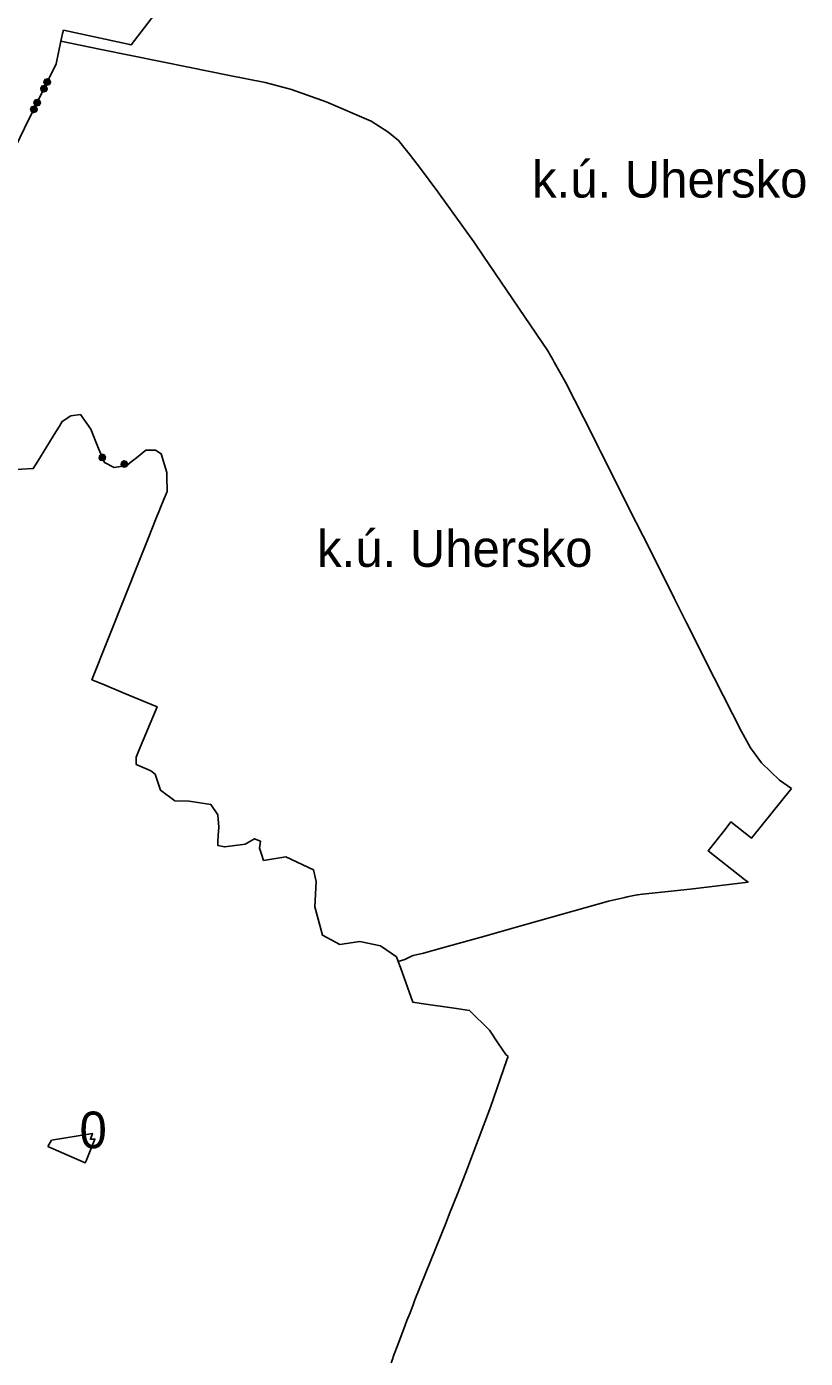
# Model space of a CAD drawing. Extents: x -633893 to -630895, y -1069360 to -1065553.
# Drawn here: x -631779 to -630930, y -1068278 to -1066826 of the extents above; entities that cross this region are included whole.
import ezdxf

# ---------------------------------------------------------------- set-up
doc = ezdxf.new("R2010")
doc.units = 0
for name, color, linetype in [('HRA_KU', 7, 'Continuous'), ('Level 255', 7, 'Continuous'), ('OVNE_PRE', 7, 'Continuous'), ('OVNI_POP', 7, 'Continuous'), ('OVNI_SET', 7, 'Continuous')]:
    doc.layers.add(name, color=color, linetype=linetype)

msp = doc.modelspace()

# ---------------------------------------------------------------- linework, layer by layer
at = {"layer": 'HRA_KU'}
for points in [[(-631889.4, -1067314.4), (-631867.8, -1067252.2), (-631854.9, -1067204.9), (-631851.7, -1067193.5), (-631846.1, -1067157.2), (-631844.8, -1067152), (-631838.9, -1067129.9), (-631829.2, -1067093), (-631816.3, -1067044.3), (-631810.3, -1067021.7), (-631800.1, -1066987.2), (-631791.3, -1066957.2), (-631781.2, -1066936.4), (-631746.9, -1066866.1), (-631741.5, -1066841.4)], [(-631762.5, -1066890.6), (-631759.9, -1066889.8), (-631757.5, -1066890.9), (-631756.6, -1066893.5), (-631757.8, -1066895.9), (-631760.3, -1066896.8), (-631762.8, -1066895.6), (-631763.6, -1066893.1), (-631762.5, -1066890.6), (-631762.2, -1066891.1), (-631763.3, -1066893.2), (-631762.9, -1066894.3), (-631761.2, -1066890.7), (-631760.1, -1066890.3), (-631762.5, -1066895.4), (-631761.8, -1066895.7), (-631759.4, -1066890.7), (-631758.7, -1066891), (-631761.1, -1066896.1), (-631760.4, -1066896.4), (-631757.9, -1066891.4), (-631757.6, -1066892.5), (-631759.3, -1066896.1), (-631758.3, -1066895.7), (-631757.2, -1066893.5)], [(-631758.9, -1066883.3), (-631756.3, -1066882.4), (-631753.9, -1066883.6), (-631753, -1066886.1), (-631754.2, -1066888.5), (-631756.8, -1066889.4), (-631759.2, -1066888.2), (-631760.1, -1066885.7), (-631758.9, -1066883.3), (-631758.6, -1066883.7), (-631759.7, -1066885.9), (-631759.3, -1066886.9), (-631757.6, -1066883.3), (-631756.5, -1066883), (-631759, -1066888), (-631758.2, -1066888.4), (-631755.8, -1066883.3), (-631755.1, -1066883.7), (-631757.5, -1066888.7), (-631756.8, -1066889.1), (-631754.4, -1066884), (-631754, -1066885.1), (-631755.7, -1066888.7), (-631754.7, -1066888.3), (-631753.6, -1066886.2)], [(-631769.8, -1066905.8), (-631767.3, -1066904.9), (-631764.8, -1066906.1), (-631764, -1066908.6), (-631765.2, -1066911), (-631767.7, -1066911.9), (-631770.1, -1066910.7), (-631771, -1066908.2), (-631769.8, -1066905.8), (-631769.5, -1066906), (-631770.5, -1066908.2), (-631770.2, -1066909.2), (-631768.4, -1066905.6), (-631767.4, -1066905.3), (-631769.8, -1066910.3), (-631769.1, -1066910.7), (-631766.6, -1066905.6), (-631765.9, -1066906), (-631768.4, -1066911), (-631767.7, -1066911.4), (-631765.2, -1066906.3), (-631764.8, -1066907.4), (-631766.6, -1066911), (-631765.5, -1066910.6), (-631764.5, -1066908.5)], [(-631773.4, -1066913.1), (-631770.9, -1066912.2), (-631768.4, -1066913.4), (-631767.6, -1066916), (-631768.7, -1066918.4), (-631771.3, -1066919.3), (-631773.7, -1066918.1), (-631774.6, -1066915.5), (-631773.4, -1066913.1), (-631773.1, -1066913.4), (-631774.1, -1066915.5), (-631773.8, -1066916.6), (-631772, -1066913), (-631770.9, -1066912.6), (-631773.4, -1066917.7), (-631772.7, -1066918), (-631770.2, -1066913), (-631769.5, -1066913.3), (-631772, -1066918.4), (-631771.2, -1066918.7), (-631768.8, -1066913.7), (-631768.4, -1066914.8), (-631770.2, -1066918.4), (-631769.1, -1066918), (-631768.1, -1066915.8)], [(-631797.1, -1067308.9), (-631771.7, -1067307.4), (-631766.7, -1067299.3), (-631747, -1067267.3), (-631743.3, -1067261.3), (-631740.1, -1067256), (-631730.9, -1067250.1), (-631720.4, -1067248.6), (-631709.1, -1067264.5), (-631700.5, -1067285.5), (-631694.2, -1067300.8), (-631683.7, -1067306.3), (-631669.6, -1067304.1), (-631664.9, -1067300.2), (-631659.1, -1067295.6), (-631649, -1067287.4), (-631638.6, -1067287.2), (-631632.4, -1067291.2), (-631626.2, -1067311.8), (-631626.1, -1067316.1), (-631625.9, -1067332.3), (-631629.7, -1067341.8), (-631632.9, -1067349.8), (-631634.8, -1067354.6), (-631636.2, -1067358), (-631638.3, -1067363.5), (-631645.7, -1067382), (-631658, -1067412.7), (-631670.1, -1067443.1), (-631690.7, -1067494.9), (-631707.8, -1067537.7), (-631695.9, -1067542.7), (-631673.6, -1067551.9), (-631636.7, -1067567.1), (-631656.6, -1067614.8), (-631659.7, -1067622.2), (-631659.4, -1067630), (-631646.8, -1067635.5), (-631643.7, -1067636.9), (-631638.8, -1067640.7), (-631635, -1067652.6), (-631633.2, -1067658.2), (-631617.5, -1067669.8), (-631601.6, -1067670.1), (-631578, -1067673.9), (-631570.5, -1067684.9), (-631569.5, -1067698.5), (-631570, -1067707.6), (-631570.4, -1067714.4), (-631570.6, -1067718.3), (-631563.4, -1067720), (-631543.1, -1067717.4), (-631540.7, -1067717.1), (-631530.4, -1067711.1), (-631524, -1067713.9), (-631525.2, -1067721.4), (-631522.9, -1067728), (-631520.6, -1067734.8), (-631496.5, -1067730.8), (-631466.1, -1067745.1), (-631463.2, -1067757.7), (-631464.9, -1067785.2), (-631456.5, -1067816.4), (-631437.6, -1067826.3), (-631415.7, -1067823.2), (-631393.3, -1067828), (-631375.6, -1067839.9), (-631373.8, -1067845.1)], [(-631694.3, -1067292.6), (-631693, -1067295), (-631693.8, -1067297.6), (-631696.1, -1067298.8), (-631698.7, -1067298.1), (-631700, -1067295.7), (-631699.2, -1067293.1), (-631696.9, -1067291.8), (-631694.3, -1067292.6), (-631694.5, -1067293), (-631696.8, -1067292.3), (-631697.8, -1067292.8), (-631693.9, -1067294), (-631693.4, -1067295), (-631698.8, -1067293.4), (-631699, -1067294.1), (-631693.6, -1067295.7), (-631693.9, -1067296.5), (-631699.2, -1067294.9), (-631699.5, -1067295.7), (-631694.1, -1067297.3), (-631695.1, -1067297.8), (-631698.9, -1067296.7), (-631698.4, -1067297.7), (-631696.1, -1067298.3)], [(-631670.3, -1067299.8), (-631669, -1067302.1), (-631669.8, -1067304.7), (-631672.2, -1067306), (-631674.8, -1067305.2), (-631676, -1067302.9), (-631675.3, -1067300.3), (-631672.9, -1067299), (-631670.3, -1067299.8), (-631670.7, -1067300.1), (-631673, -1067299.4), (-631674, -1067299.9), (-631670.2, -1067301.1), (-631669.6, -1067302.1), (-631675, -1067300.5), (-631675.2, -1067301.2), (-631669.9, -1067302.8), (-631670.1, -1067303.6), (-631675.5, -1067302), (-631675.7, -1067302.8), (-631670.3, -1067304.4), (-631671.3, -1067304.9), (-631675.2, -1067303.8), (-631674.6, -1067304.8), (-631672.3, -1067305.4)]]:
    msp.add_lwpolyline(points, dxfattribs=at)
at = {"layer": 'Level 255'}
msp.add_line((-630945, -1067656.3), (-630945, -1067656.3), dxfattribs=at)
at = {"layer": 'OVNE_PRE'}
for points in [[(-631738.9, -1066829.4), (-631666.6, -1066845.1), (-631665.1, -1066845.4), (-631614.1, -1066778.7), (-631613.5, -1066777.9), (-631589.8, -1066737.2), (-631572.1, -1066700.9), (-631561.1, -1066702.2), (-631444.8, -1066753.8), (-631417.5, -1066761.8)], [(-631738.9, -1066829.4), (-631739.7, -1066832.9), (-631740.8, -1066838.1), (-631741.5, -1066841.4), (-631697.7, -1066850.5), (-631600.6, -1066870), (-631559.5, -1066878.3), (-631519.1, -1066886.4), (-631506.5, -1066889.8), (-631490.2, -1066894.1), (-631452.5, -1066907.4), (-631403.2, -1066928.7), (-631385.2, -1066940.1), (-631373.7, -1066949.8), (-631360.5, -1066966), (-631349.6, -1066980.4), (-631330.6, -1067005.8), (-631328.9, -1067008.1), (-631291.5, -1067060.3), (-631280.8, -1067076), (-631210.7, -1067178.9), (-631207.5, -1067184.8), (-631205.4, -1067188.4), (-631203.7, -1067191.5), (-631191.4, -1067213.4), (-631181.7, -1067232.6), (-631161.8, -1067271.7), (-631155.1, -1067285.2), (-631153.7, -1067288), (-631144.4, -1067306.6), (-631121.7, -1067352.2), (-631107, -1067381.3), (-631074.3, -1067446.2), (-631073.1, -1067448.6), (-631059.5, -1067475.5), (-631029.3, -1067535.5), (-630999.5, -1067594), (-630989.8, -1067611.9), (-630977.8, -1067628.3), (-630958.2, -1067647.1), (-630945, -1067656.3)], [(-630945, -1067656.3), (-630988.6, -1067710.4), (-631011.1, -1067692.7), (-631017.5, -1067700.9), (-631035.9, -1067724.3), (-630996.5, -1067755.4), (-630992.4, -1067758.4), (-631055.5, -1067766.1), (-631107.6, -1067771.5), (-631113.1, -1067772.1), (-631113.5, -1067772.2), (-631124.3, -1067774.5), (-631126.7, -1067775), (-631144.7, -1067779), (-631222, -1067800.9), (-631260.6, -1067812), (-631276.9, -1067816.6), (-631325.5, -1067830), (-631346.4, -1067835.7), (-631357.7, -1067838.6), (-631359.5, -1067839.1), (-631361, -1067839.9), (-631366.5, -1067842.8), (-631373.8, -1067845.1)], [(-631254.1, -1067948.4), (-631256.4, -1067946.5), (-631264.4, -1067934.6), (-631274.4, -1067919.9), (-631296.2, -1067898.3), (-631310.3, -1067896.2), (-631348.8, -1067890.7), (-631357.8, -1067889.4), (-631371.5, -1067851.5), (-631373.8, -1067845.1)], [(-631381.4, -1068282.5), (-631379.7, -1068277.7), (-631379.2, -1068276.2), (-631373.2, -1068260.1), (-631366.3, -1068241.5), (-631364.3, -1068236.6), (-631361, -1068228.2), (-631357.2, -1068218.2), (-631355.6, -1068214), (-631321.7, -1068129.5), (-631317.9, -1068119.9), (-631309.4, -1068098.2), (-631300.3, -1068074.9), (-631273.3, -1068003.7), (-631255.5, -1067952.1), (-631254.1, -1067948.4)]]:
    msp.add_lwpolyline(points, dxfattribs=at)
at = {"layer": 'OVNI_SET'}
msp.add_lwpolyline([(-631755.8, -1068046.8), (-631715, -1068064.4), (-631714.2, -1068062.4), (-631704.6, -1068038.6), (-631709.4, -1068038.8), (-631707, -1068032.7), (-631751.8, -1068039.8), (-631755.8, -1068046.8)], dxfattribs=at)

# ---------------------------------------------------------------- texts
at = {"layer": 'Level 255'}
for p in [(-631228, -1067011.9), (-631462.3, -1067414.6)]:
    msp.add_text('k.ú. Uhersko', height=40, dxfattribs=at).set_placement(p)
at = {"layer": 'OVNI_POP'}
msp.add_text('0', height=40, dxfattribs=at).set_placement((-631721.3, -1068048.6))

doc.saveas('drawing.dxf')
